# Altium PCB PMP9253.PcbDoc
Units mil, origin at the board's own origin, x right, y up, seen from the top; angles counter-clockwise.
Board outline 3700 x 3100 mil, 4 copper layers (Top Layer, MidLayer1, MidLayer2, Bottom Layer), stack 90 mil thick; 71 components, 28 nets, 219 pads, 12 vias.
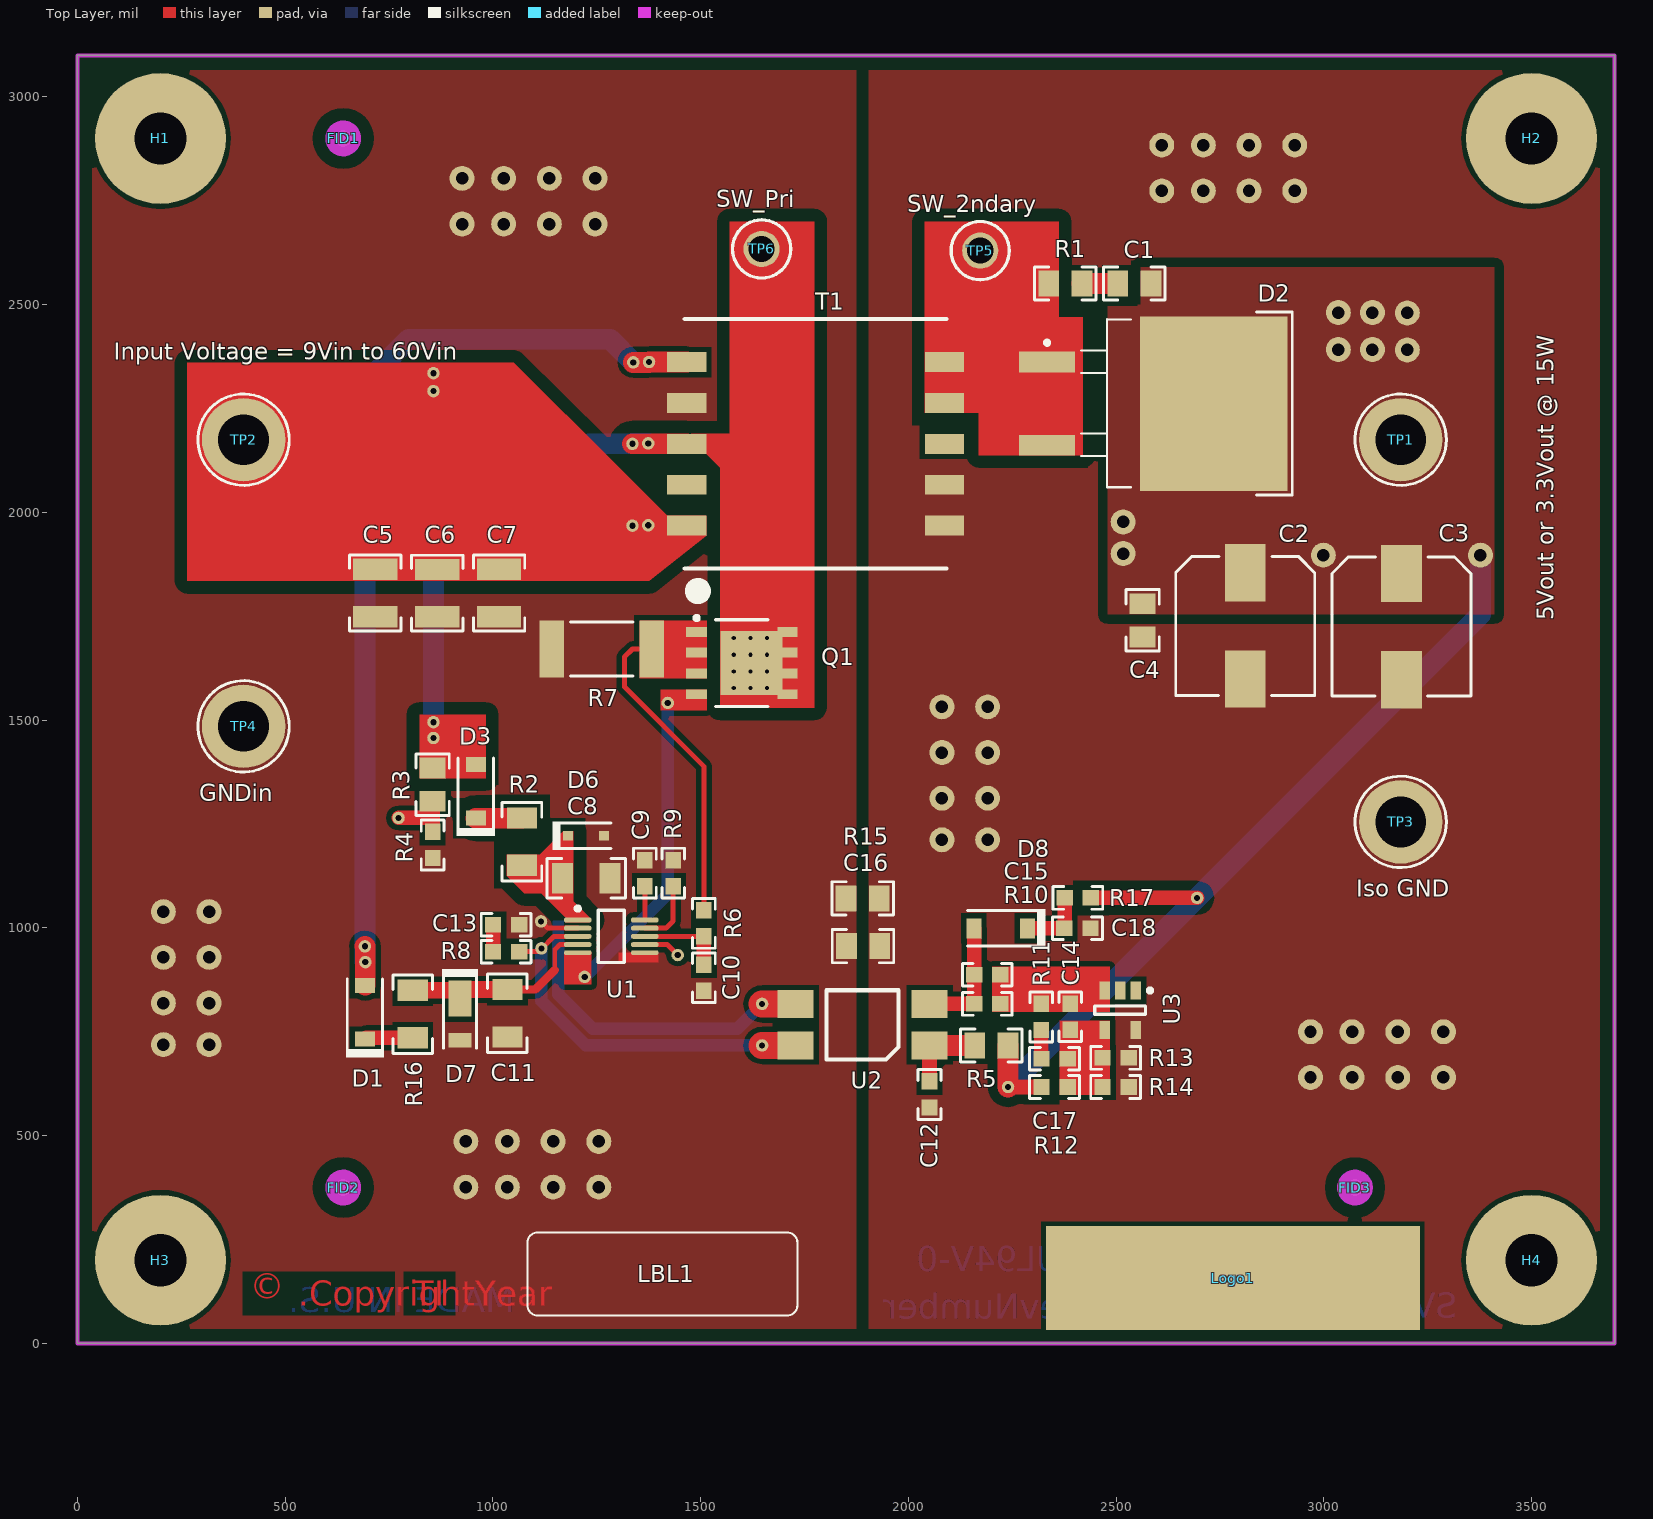
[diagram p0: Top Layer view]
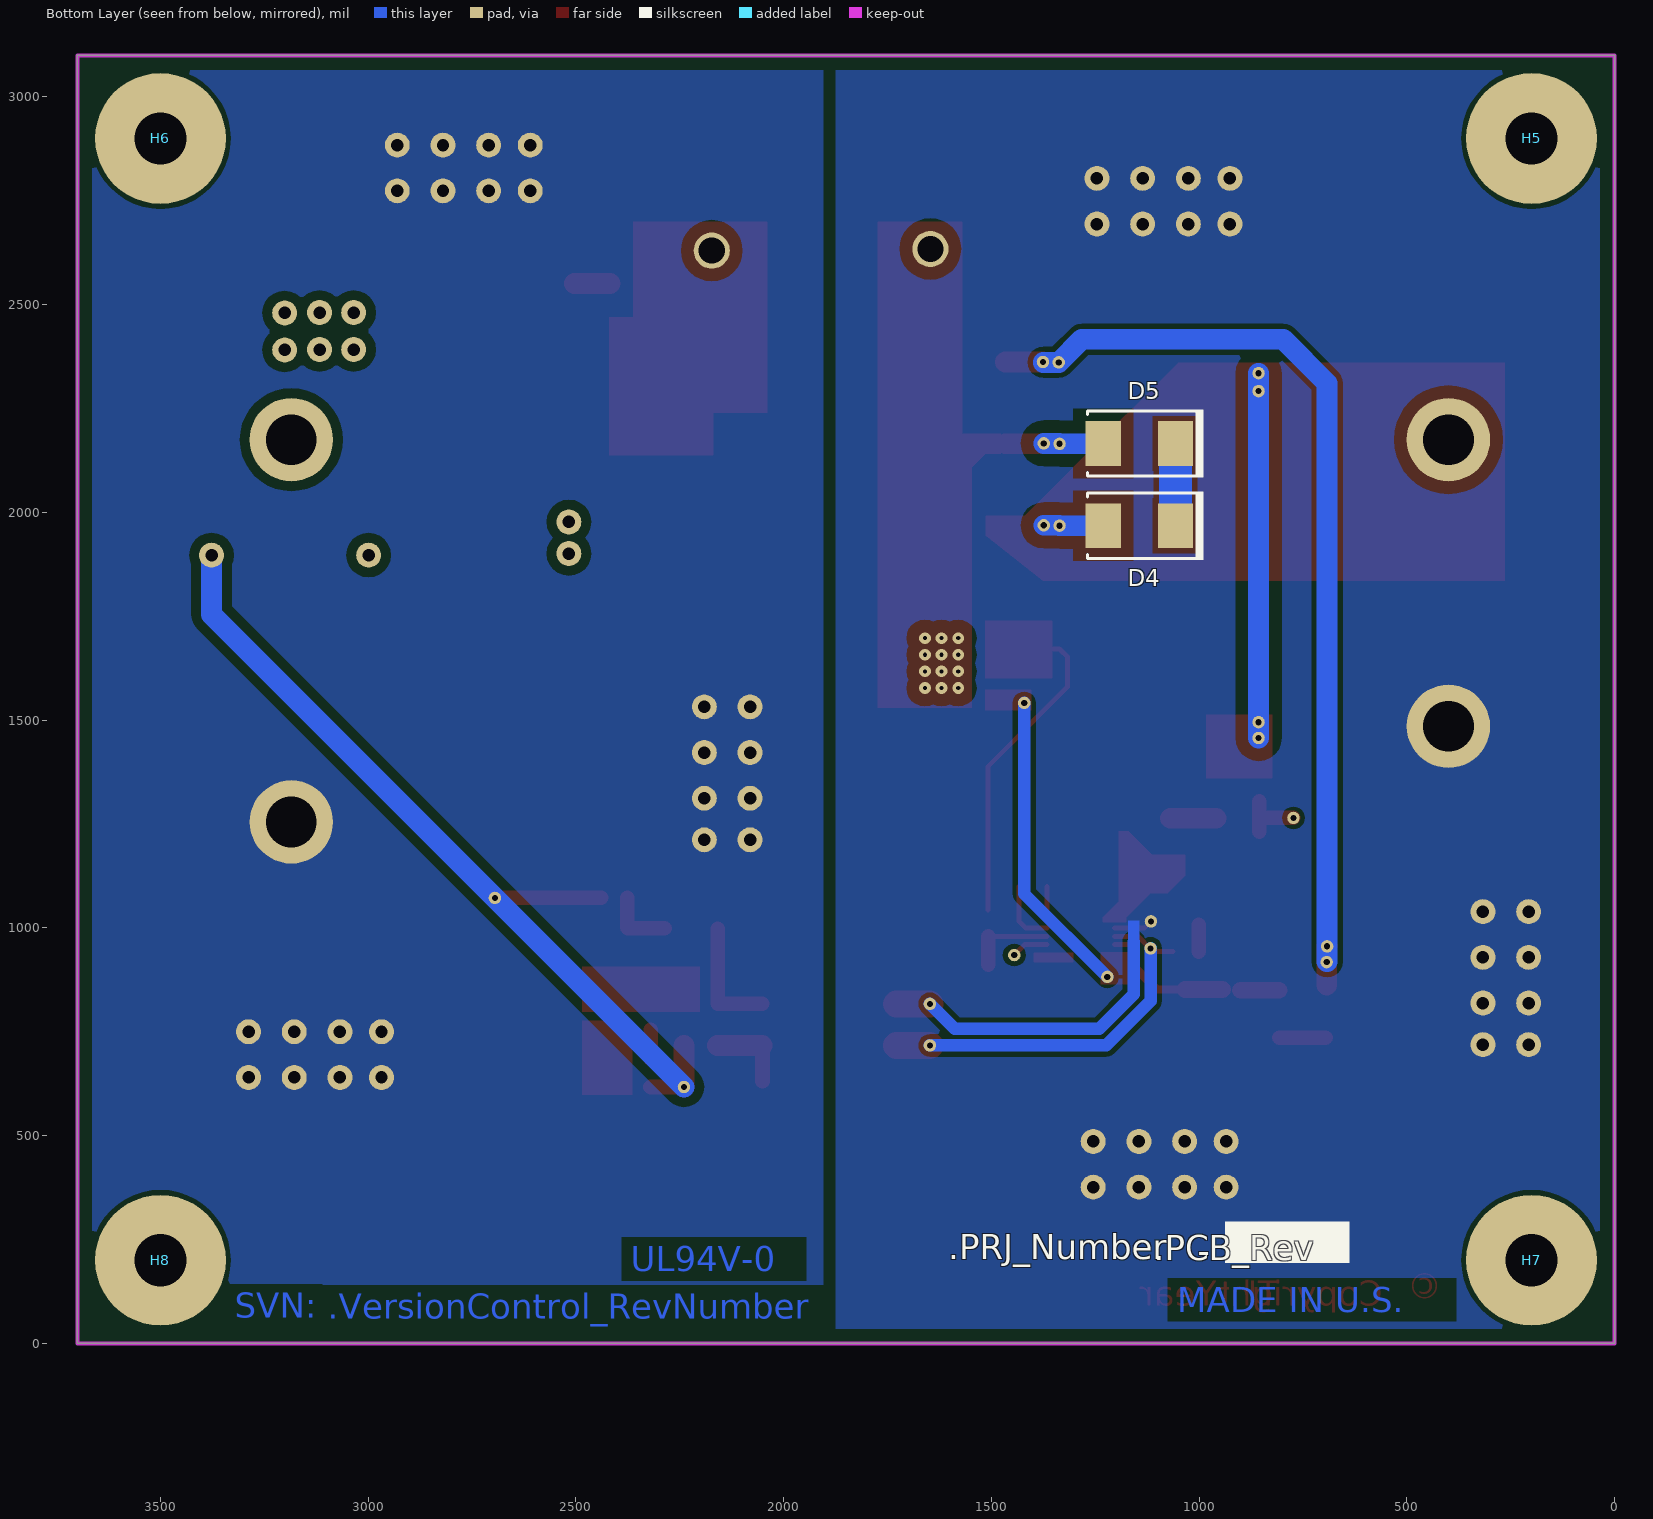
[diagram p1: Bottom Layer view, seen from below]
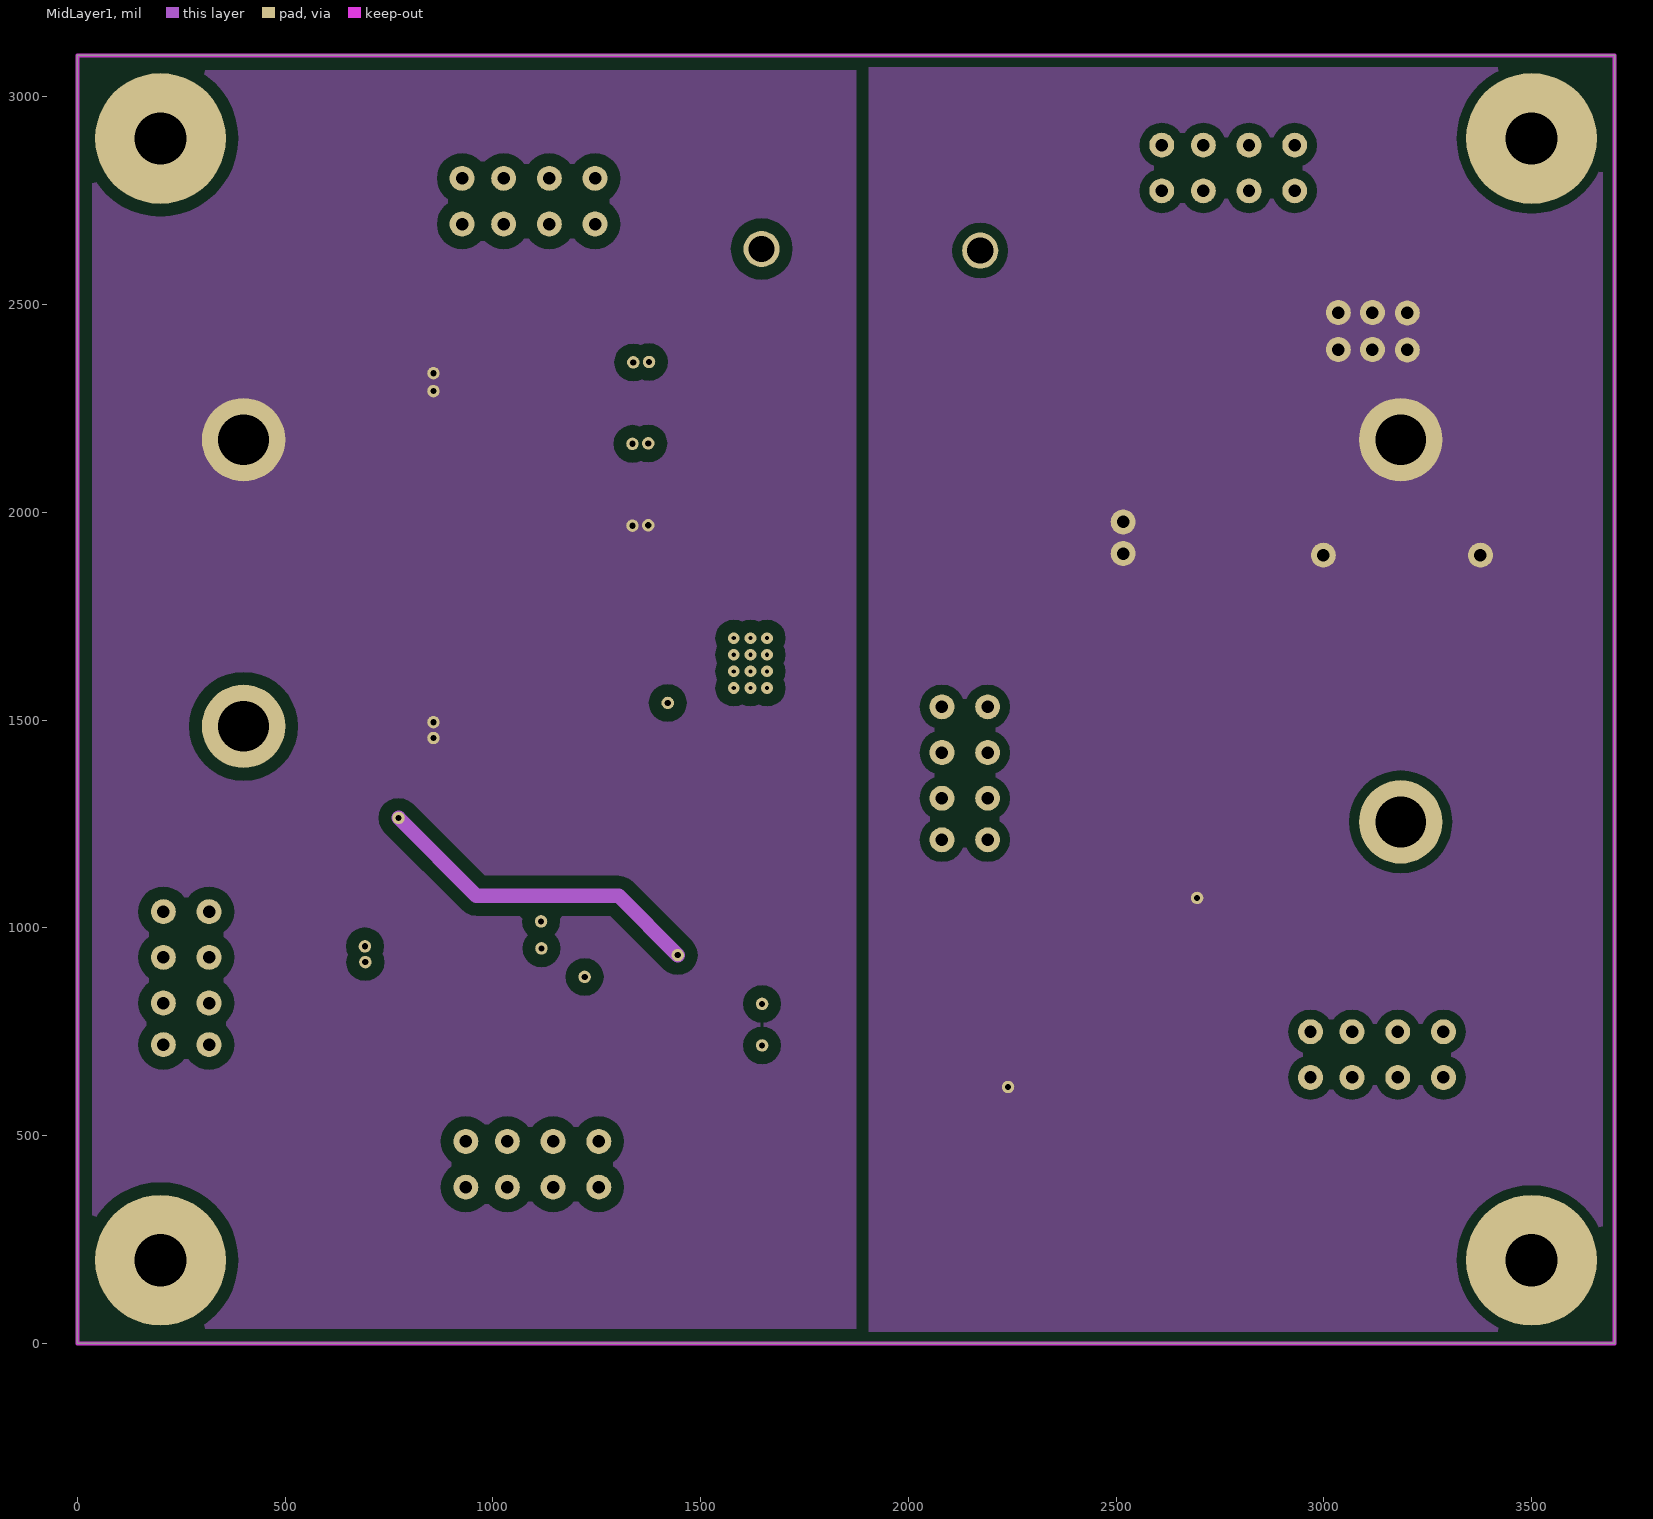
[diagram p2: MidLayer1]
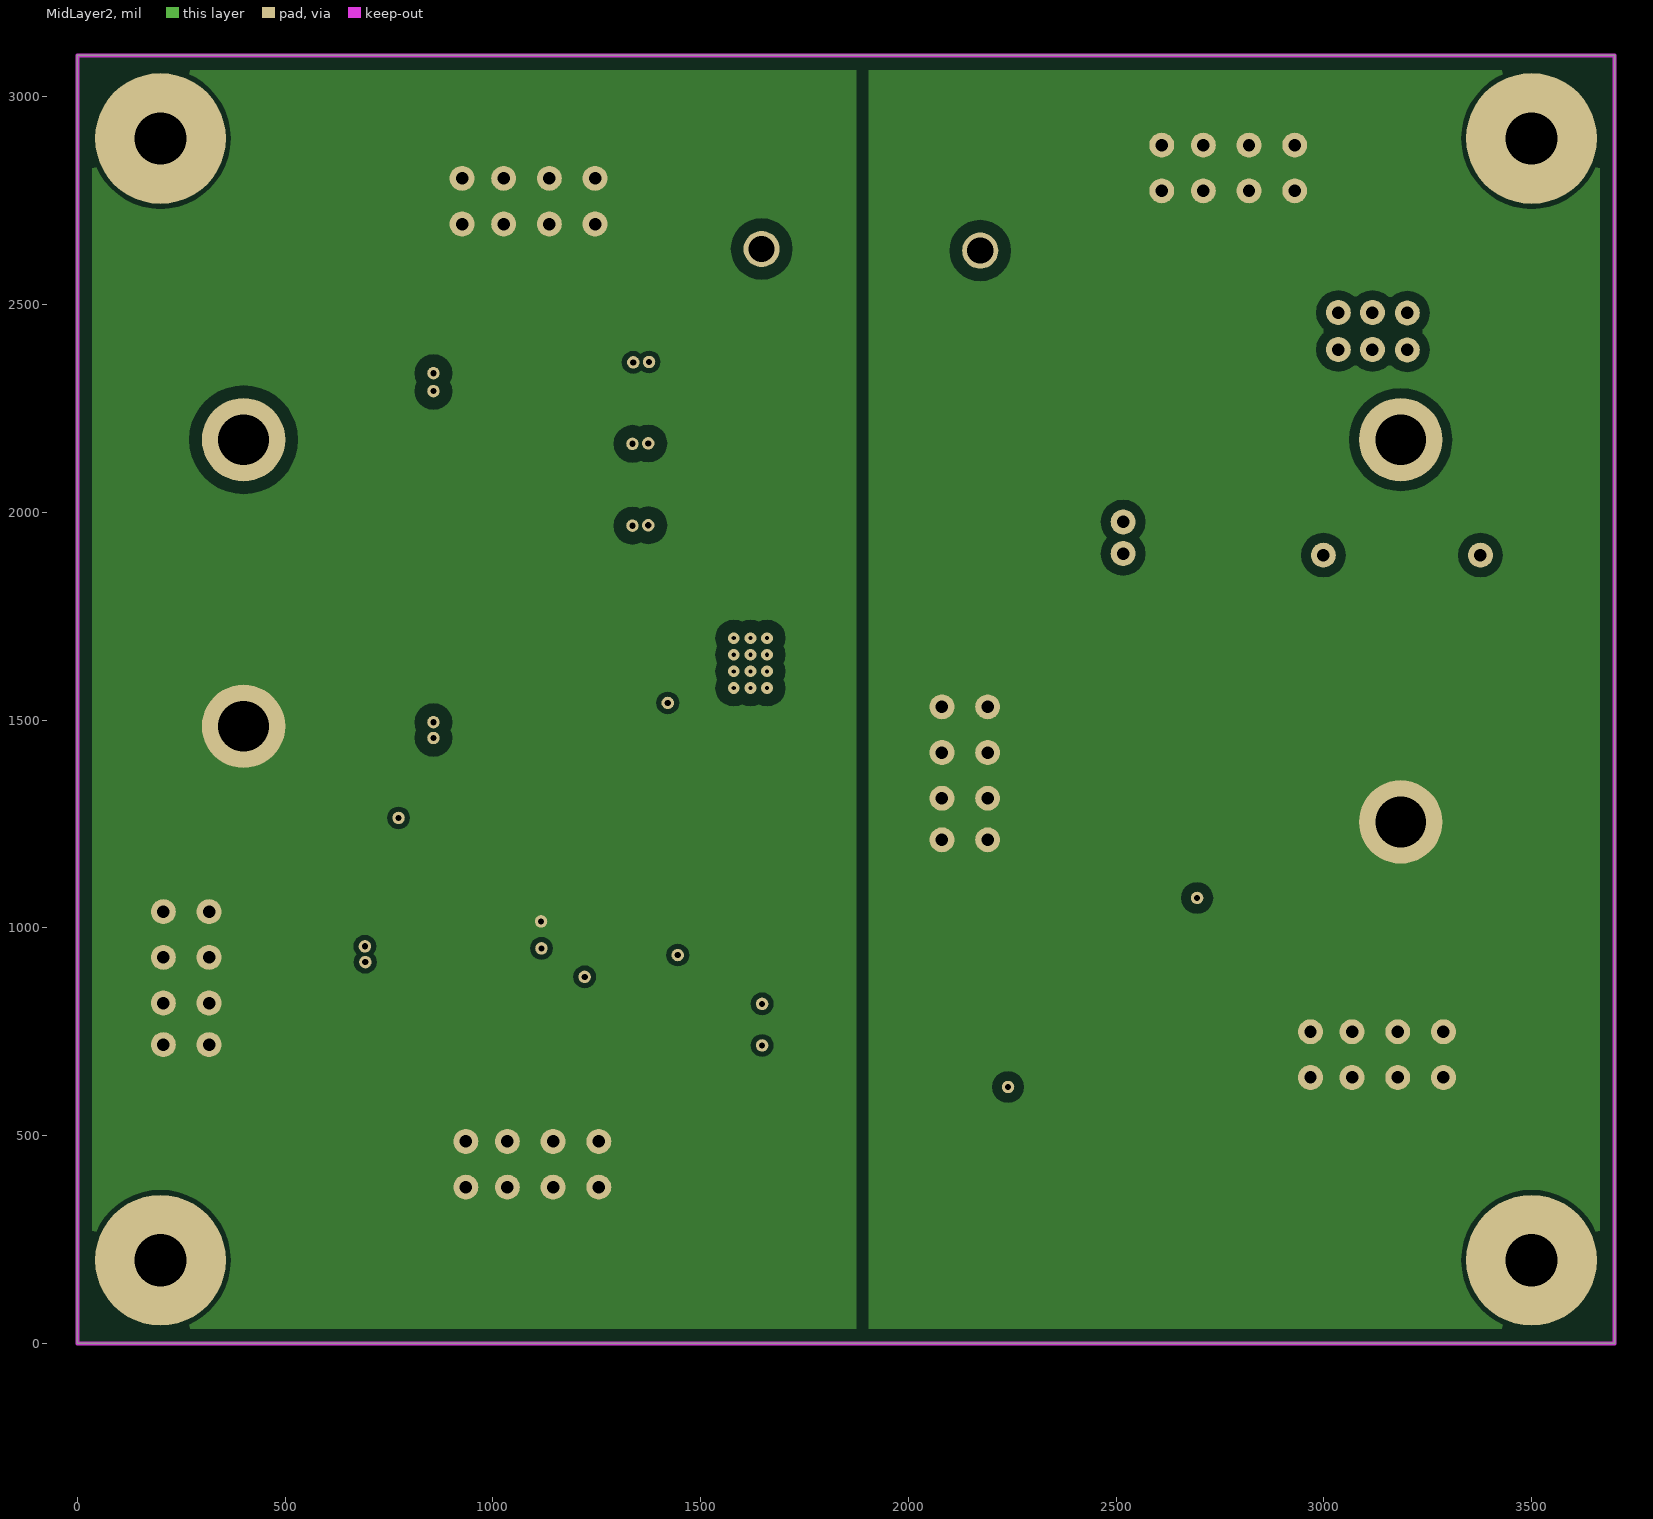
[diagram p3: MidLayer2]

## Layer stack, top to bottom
Top Solder: solder mask 0.4, Solder Resist, Dk 3.5
Top Layer: signal copper 1.4
Dielectric1: core 59.2, FR-4, Dk 4.8
MidLayer1: signal copper 1.4
Dielectric2: prepreg 12.6, FR-4, Dk 4.8
MidLayer2: signal copper 1.4
Dielectric3: core 12.6, FR-4, Dk 4.8
Bottom Layer: signal copper 1.4
Bottom Solder: solder mask 0.4, Solder Resist, Dk 3.5

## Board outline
0,0 3700,0 3700,3100 0,3100

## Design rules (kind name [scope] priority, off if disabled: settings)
AcuteAngle [All] p1: minimum=4.50000000000000E+0001 checktracksonly=FALSE
AssemblyTestPointUsage [All] p1: valid=2
Clearance Clearance_HV_Vout [InNet('VOUT')] p1: gap=23 ignorepadtopadclearanceinfootprint=FALSE except(0: Arc-Hole Track-Hole SMDPad-Hole THPad-Hole Via-Hole Fill-Hole Poly-Hole Region-Hole Text-Hole)
Clearance Clearance_HV_Vout_PreRect [InNet('VOUT_PRERECT')] p2: gap=30 ignorepadtopadclearanceinfootprint=FALSE except(0: Arc-Hole Track-Hole SMDPad-Hole THPad-Hole Via-Hole Fill-Hole Poly-Hole Region-Hole Text-Hole)
Clearance Clearance_HV_SW [InNet('SW')] p3: gap=30 ignorepadtopadclearanceinfootprint=FALSE except(0: Arc-Hole Track-Hole SMDPad-Hole THPad-Hole Via-Hole Fill-Hole Poly-Hole Region-Hole Text-Hole)
Clearance Clearance_HV_VinMain [InNet('VIN_MAIN')] p4: gap=30 ignorepadtopadclearanceinfootprint=FALSE except(0: Arc-Hole Track-Hole SMDPad-Hole THPad-Hole Via-Hole Fill-Hole Poly-Hole Region-Hole Text-Hole)
Clearance Clearance_HV_VinRectified [InNet('VIN_RECTIFIED')] p5: gap=30 ignorepadtopadclearanceinfootprint=FALSE except(0: Arc-Hole Track-Hole SMDPad-Hole THPad-Hole Via-Hole Fill-Hole Poly-Hole Region-Hole Text-Hole)
Clearance Clearance_HV_Vin [InNet('VIN')] p6: gap=30 ignorepadtopadclearanceinfootprint=FALSE except(0: Arc-Hole Track-Hole SMDPad-Hole THPad-Hole Via-Hole Fill-Hole Poly-Hole Region-Hole Text-Hole)
Clearance Clearance_BoardEdge_MountingHoles [OnCopper and InComponentClass('Mounting Holes') vs IsKeepOut] p7: gap=35 ignorepadtopadclearanceinfootprint=FALSE except(0: Arc-Hole Track-Hole SMDPad-Hole THPad-Hole Via-Hole Fill-Hole Poly-Hole Region-Hole Text-Hole)
Clearance Clearance_BoardEdge_Poly [OnCopper and InPoly vs IsKeepOut] p8: gap=30 ignorepadtopadclearanceinfootprint=FALSE except(0: Arc-Hole Track-Hole SMDPad-Hole THPad-Hole Via-Hole Fill-Hole Poly-Hole Region-Hole Text-Hole)
Clearance Clearance_BoardEdge [OnCopper and Not InComponentClass('Logo') and not InComponentClass('FiducialMark') and not InRegion(1000,500,4000,800) and Not IsKeepout vs IsKeepOut] p9: gap=30 ignorepadtopadclearanceinfootprint=FALSE except(0: Arc-Hole Track-Hole SMDPad-Hole THPad-Hole Via-Hole Fill-Hole Poly-Hole Region-Hole Text-Hole)
Clearance Clearance_Poly [InPolygon] p10: gap=12 ignorepadtopadclearanceinfootprint=FALSE except(0: Arc-Hole Track-Hole SMDPad-Hole THPad-Hole Via-Hole Fill-Hole Poly-Hole Region-Hole Text-Hole)
Clearance [All] p11: gap=10 ignorepadtopadclearanceinfootprint=FALSE except(0: Arc-Hole Track-Hole SMDPad-Hole THPad-Hole Via-Hole Fill-Hole Poly-Hole Region-Hole Text-Hole)
ComponentClearance ComponentClearance_Logo [InComponentClass(Logo)] p1: gap=50 collisioncheckmode=3 verticalgap=10 showdistances=FALSE
ComponentClearance ComponentClearance_ScrewToNut [(HasFootprint('NY PMS 440 0025 PH')) vs (HasFootprint('Keystone_1902C'))] p2: gap=5 collisioncheckmode=3 verticalgap=10 showdistances=FALSE
ComponentClearance ComponentClearance_MountingHoles [InComponentClass('Mounting Holes')] p3: gap=250 collisioncheckmode=3 verticalgap=100000 showdistances=FALSE
ComponentClearance ComponentClearance_SmallPassives [HasFootprint('0201*') or HasFootprint('0402*') or HasFootprint('0508') or HasFootprint('0603*') or HasFootprint('0612') or HasFootprint('0805*') or HasFootprint('0815*') or HasFootprint('0830*') or HasFootprint('1206*') or HasFootprint('1210*') or HasFootprint('1808*') or HasFootprint('1812*') or HasFootprint('1825*') or HasFootprint('2010*') or HasFootprint('2220*') or HasFootprint('2225*') or HasFootprint('2512*') or HasFootprint('2728*') or HasFootprint('3518*') vs HasFootprint('0201*') or HasFootprint('0402*') or HasFootprint('0508') or HasFootprint('0603*') or HasFootprint('0612') or HasFootprint('0805*') or HasFootprint('0815*') or HasFootprint('0830*') or HasFootprint('1206*') or HasFootprint('1210*') or HasFootprint('1808*') or HasFootprint('1812*') or HasFootprint('1825*') or HasFootprint('2010*') or HasFootprint('2220*') or HasFootprint('2225*') or HasFootprint('2512*') or HasFootprint('2728*') or HasFootprint('3518*')] p4: gap=20 collisioncheckmode=3 verticalgap=10 showdistances=FALSE
ComponentClearance ComponentClearance_THtoSMT [IsThruComponent vs IsSMTComponent] p5: gap=100 collisioncheckmode=3 verticalgap=100000 showdistances=FALSE
ComponentClearance ComponentClearance_THtoTH [IsThruComponent vs IsThruComponent] p6: gap=118.11 collisioncheckmode=3 verticalgap=100000 showdistances=FALSE
ComponentClearance [All] p7: gap=40 collisioncheckmode=3 verticalgap=10 showdistances=FALSE
DiffPairsRouting [All] p1: maxlimit=100 minlimit=10 mostfreqgap=10 toplayer_minwidth=15 toplayer_maxwidth=15 toplayer_prefwidth=15 midlayer1_minwidth=15 midlayer1_maxwidth=15 midlayer1_prefwidth=15 midlayer2_minwidth=15 midlayer2_maxwidth=15 midlayer2_prefwidth=15 bottomlayer_minwidth=15 bottomlayer_maxwidth=15 bottomlayer_prefwidth=15 maxuncoupledlength=1000
FabricationTestPointUsage TestPointUsage [All] p1: valid=2 allowmultiple=FALSE
FabricationTestpoint Testpoint [All] p1: side=3 testpointundercomponent=TRUE minsize=40 maxsize=100 preferedsize=60 minholesize=0 maxholesize=40 preferedholesize=32 testpointgrid=1 allowsidetop=TRUE allowsidebottom=TRUE usegrid=TRUE gridtolerance=0.01
FanoutControl Fanout_LCC [IsLCC] p1: bgadir=Out bgaviamode=Centered fanoutstyle=Auto fanoutdirection=Alternating viagrid=1 // Fanout_LCC (Default Rule)
FanoutControl Fanout_BGA [IsBGA] p2: bgadir=Out bgaviamode=Centered fanoutstyle=Auto fanoutdirection=Alternating viagrid=1 // Fanout_BGA (Default Rule)
FanoutControl Fanout_Default [All] p4: bgadir=Out bgaviamode=Centered fanoutstyle=Auto fanoutdirection=Alternating viagrid=1 // Fanout_Default (Default Rule)
FanoutControl Fanout_Small [(CompPinCount < 5)] p5: bgadir=Out bgaviamode=Centered fanoutstyle=Auto fanoutdirection=OutThenIn viagrid=1 // Fanout_Small (Default Rule)
HoleSize [All] p1: absolutevalues=TRUE maxlimit=251 minlimit=10 maxpercent=80.000 minpercent=20.000
MinimumAnnularRing [All] p1: minimumring=5
MinimumSolderMaskSliver MinimumSolderMaskSliver_Logo [InComponentClass('Logo') vs InComponentClass('Logo')] p1: minsoldermaskwidth=0.7
MinimumSolderMaskSliver [All] p2: minsoldermaskwidth=4
PlaneClearance [All] p1: clearance=12
PlaneConnect [All] p1: planeconnectstyle=Direct reliefexpansion=10 reliefentries=4 reliefconductorwidth=10 reliefairgap=10
PolygonConnect [All] p1: connectstyle=Direct reliefconductorwidth=10 reliefentries=4 polygonreliefangle="90 Angle" airgapwidth=10
RoutingVias [All] p1: holewidth=16 width=34 viastyle="Through Hole" minholewidth=8 minwidth=26 maxholewidth=40 maxwidth=65
SMDToCorner [All] p1: distance=30000
SilkToSilkClearance [All] p1: silktosilkclearance=5
SilkToSolderMaskClearance SilkscreenOverComponentPads [IsPad] p1: minsilkscreentomaskgap=5 clearancetoexposedcopper=TRUE
SolderMaskExpansion [All] p1: expansion=3
Width [All] p1: maxlimit=100 minlimit=6 preferedwidth=10 checkconnectedcopper=TRUE
15 further rules are at their usual default settings.

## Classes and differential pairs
component class "PMP9253 schematic Rev3": C1 C2 C3 C4 C5 C6 C7 C8 C9 C10 C11 C12 C13 C14 C15 C16 C17 C18 D1 D2 D3 D4 D5 D6 D7 D8 Q1 R1 R2 R3 R4 R5 R6 R7 R8 R9 R10 R11 R12 R13 R14 R15 R16 R17 T1 TP1 TP2 TP3 TP4 TP5 TP6 U1 U2 U3
component class Label: LBL1
component class AssemblyNote: ZZ1 ZZ2 ZZ3 ZZ4
component class FiducialMark: FID1 FID2 FID3
component class PMP9253_Hardware_ANSI-B: FID1 FID2 FID3 H1 H2 H3 H4 H5 H6 H7 H8 LBL1 Logo1 ZZ1 ZZ2 ZZ3 ZZ4
component class Logo: Logo1
component class "Mounting Holes": H1 H2 H3 H4

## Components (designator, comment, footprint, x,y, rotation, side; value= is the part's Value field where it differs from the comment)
C1 "DNP" 0805_HV 2544,2551 r180 top
C2 "Santo, 10SVP330M" SM_RADIAL_8MM 2811,1727 r270 top
C3 "Santo, 10SVP330M" SM_RADIAL_8MM 3187,1725 r270 top
C4 "GRM21BR71A106KE51L" 0805_HV 2564,1740 r270 top
C5 "Yuden, HMK325B7225KN-T" 1210 717,1806 r270 top
C6 "HMK325B7225KN-T" 1210 866,1805.69 r270 top
C7 "HMK325B7225KN-T" 1210 1015,1806 r270 top
C8 "C3216X7R2A105M" 1206 1225,1119.56 r0 top
C9 "C1608C0G1E103J" 0603 1366,1131.56 r90 top
C10 "06035A101JAT2A" 0603 1508,880 r270 top
C11 "GRM31CR71E106KA12L" 1206 1035,794.56 r270 top
C12 "C1608X7R1C105K" 0603 2051,599.01 r90 top
C13 "06033C104JAT2A" 0603 1032,1007.76 r0 top
C14 "06033C101KAT2A" 0603 2390,786.01 r90 top
C15 "DNP" 0603 2190,887.01 r180 top
C16 "C2012C0G2E102J" 0805_HV 1891,956 r180 top
C17 "GRM188R61A474KA61D" 0603 2352,685.01 r180 top
C18 "C1608X7R1C105K" 0603 2407,999 r180 top
D1 "1N4148W-7-F" SOD-123 692,796.56 r90 top
D2 "MBRB1545CT-T" DDPAK 2580,2262 r0 top
D3 "1N4148W-7-F" SOD-123 959,1328.56 r90 top
D4 "DNP" SMB 1144,1968 r0 bottom
D5 "DNP" SMB 1144,2166 r0 bottom
D6 "Diodes Inc, MMSZ5231BS-7-F" sod-323 1224,1221.56 r0 top
D7 "DFLZ12-7" powerDI123 921,779.56 r270 top
D8 "1N4148W-7-F" SOD-123 2222,999 r180 top
FID1 "Fiducial" Fiducial10-20 640,2900 r0 top
FID2 "Fiducial" Fiducial10-20 640,375 r0 top
FID3 "Fiducial" Fiducial10-20 3075,375 r0 top
H1 "NY PMS 440 0025 PH" "NY PMS 440 0025 PH" 200,2900 r0 top locked
H2 "NY PMS 440 0025 PH" "NY PMS 440 0025 PH" 3500,2900 r0 top locked
H3 "NY PMS 440 0025 PH" "NY PMS 440 0025 PH" 200,200 r0 top locked
H4 "NY PMS 440 0025 PH" "NY PMS 440 0025 PH" 3500,200 r0 top locked
H5 "1902C" Keystone_1902C 200,2900 r180 bottom locked
H6 "1902C" Keystone_1902C 3500,2900 r180 bottom locked
H7 "1902C" Keystone_1902C 200,200 r180 bottom locked
H8 "1902C" Keystone_1902C 3500,200 r180 bottom locked
LBL1 "Size: 0.65\" x 0.20 \"" Label_650x200 1408,167 r0 top
Logo1 "Texas Instruments" TI_Stacked_SolderMask_Small 2781,157 r0 top
Q1 "Infineon, BSC190N15NS3" PowerPAK_SO-8 1600,1637.32 r0 top
R1 "DNP" 0805_HV 2378,2551 r0 top
R2 "CRCW12063R32FKEA" 1206 1070,1207.56 r90 top
R3 "CRCW080563K4FKEA" 0805_HV 855,1344.56 r90 top
R4 "CRCW060310K0FKEA" 0603 855,1199.56 r90 top
R5 "10" 0805_HV 2200,717.01 r0 top
R6 "CRCW06031K00FKEA" 0603 1508,1011 r90 top
R7 "RHC2512FTR100" 2512M 1262,1671.32 r0 top
R8 "CRCW06030000Z0EA" 0603 1032,942.56 r0 top
R9 "CRCW060349K9FKEA" 0603 1434,1131.56 r270 top
R10 "CRCW06031K00FKEA" 0603 2190,817.01 r180 top
R11 "CRCW06034K75FKEA" 0603 2320,785.71 r270 top
R12 "CRCW06033K01FKEA" 0603 2352,617.01 r180 top
R13 "CRCW06031K82FKEA" 0603 2499,687.01 r180 top
R14 "CRCW06032K26FKEA" 0603 2499,617.01 r180 top
R15 "CRCW08050000Z0EA" 0805_HV 1890,1071 r0 top
R16 "CRCW120649R9FKEA" 1206 807,792.56 r270 top
R17 "CRCW06033K01FKEA" 0603 2408,1072 r0 top
T1 "PA3856.001NL" PA3856.001NL 1777,2165 r270 top
TP1 "5Vout or 3.3Vout @ 15W" Keystone1503-2 3185,2175 r0 top
TP2 "Input Voltage = 9Vin to 60Vin" Keystone1503-2 400,2175 r0 top
TP3 "Iso GND" Keystone1503-2 3185,1255 r0 top
TP4 "GNDin" Keystone1503-2 400,1485 r0 top
TP5 "SW_2ndary" Keystone5014 2173,2630 r0 top
TP6 "SW_Pri" Keystone5014 1647,2634 r0 top
U1 "LM5022MM" MUB10A_N 1285,979.56 r0 top
U2 "PS2501L-1-A" PS2501L 1890,767.01 r180 top
U3 "TI, LMV431ACM5" MF05A_N 2510,802.01 r270 top
ZZ1 "This Assembly Note is for PCB labels only" AssemblyNoteLabel 185,3938 r0 top
ZZ2 "These assemblies are ESD sensitive, ESD precautions shall be observed." AssemblyNote 185,3829.11 r0 top
ZZ3 "These assemblies must be clean and free from flux and all contaminants. Use of no clean flux is not acceptable." AssemblyNote 185,3740.56 r0 top
ZZ4 "These assemblies must comply with workmanship standards IPC-A-610 Class 2., unless otherwise specified." AssemblyNote 185,3652 r0 top

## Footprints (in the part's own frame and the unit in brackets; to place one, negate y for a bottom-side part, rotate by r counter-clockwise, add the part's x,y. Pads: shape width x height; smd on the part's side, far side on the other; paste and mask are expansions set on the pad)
0603 [mm] "0603 from SM-752 data"
  rect 1x0.95 smd: 1(-0.8,0) 2(0.8,0)
  silkscreen extent -1.52,-0.69 1.52,0.69, body extent -0.87,-0.47 0.87,0.47, height 0.85
0805_HV [mil] "0805 with 30mil clearance between pads"
  rect 50x63 smd: 1(-40,0) 2(40,0)
  silkscreen extent -74,-40 74,40, body extent -43,-29 43,29, height 43
1206 [mm] "1206 from SM-752 data"
  rect 1.3x1.85 smd: 1(-1.45,0) 2(1.45,0)
  silkscreen extent -2.4,-1.21 2.4,1.21, body extent -1.7,-0.9 1.7,0.9, height 1.35
1210 [mm] "1210 from SM-752 data"
  rect 1.3x2.7 smd: 1(-1.45,0) 2(1.45,0)
  silkscreen extent -2.32,-1.57 2.32,1.57, body extent -1.7,-1.35 1.7,1.35, height 1.35
2512M [mm] "Chip Resistor, Body 6.3x3.2mm, IPC Low Density"
  rect 1.5x3.5 smd: 1(-3.05,0) 2(3.05,0)
  silkscreen extent -1.9,-1.65 1.9,1.65, body extent -3.22,-1.67 3.22,1.67, height 0.71
AssemblyNote [mil] "Assembly Note"
AssemblyNoteLabel [mil] "Assembly Note for PCB Labels"
DDPAK [mil] "D2-PAK, 3-Pads, Body 9.7x10.4mm (max), TO-263AB, using Vishay Silionix recommended pad sizes"
  rect 135x49.49 smd: 1(-246.06,100) 3(-246.06,-100)
  rect 355x420 smd paste-181.1: 4(155.51,0)
  silkscreen extent -251,-220 344,220, body extent -295,-202 324,202, height 180
Fiducial10-20 [mm]
  round 1 smd paste-0.5 mask+0.5: 1(0,0)
  Top Layer keep-out circle w1.178: c0,0 r0.5
Keystone1503-2 [mm] "Double Turret"
  round 5.1 hole 3.1: 1(0,0)
  silkscreen extent -2.79,-2.79 2.79,2.79, body extent -2.4,-2.4 2.38,2.4, height 9.22
Keystone5014 [mil] "Keystone Multipurpose loops"
  round 87 hole 63: 1(0,0)
  silkscreen extent -70,-70 70,70, body extent -63,-63 63,62, height 319
Keystone_1902C [mil] "Hex Standoff, 4-40 threaded, nylon"
  body extent -145,-126 146,126, height 501
Label_650x200 [mil] "Thermal Transfer Label"
  silkscreen extent -325,-100 325,100, body extent -325,-100 325,100, height 1
MF05A_N [mm] "SOT23, 5-Leads, Body 2.9x1.6mm, Pitch 0.95mm, Lead Span 2.8mm, IPC Medium Density"
  rect 1.1x0.65 smd: 1(-1.2,0.95) 2(-1.2,0) 3(-1.2,-0.95) 4(1.2,-0.95) 5(1.2,0.95)
  silkscreen extent -1.32,-1.55 0.25,1.95, body extent -0.9,-1.55 0.9,1.55, height 1.19
MUB10A_N [mm] "TSSOP, 10-Leads, Body 3x3mm, Pitch 0.5mm, IPC Medium Density"
  oval 1.7x0.3 smd: 1(-2.05,1) 2(-2.05,0.5) 3(-2.05,0) 4(-2.05,-0.5) 5(-2.05,-1) 6(2.05,-1) 7(2.05,-0.5) 8(2.05,0) 9(2.05,0.5) 10(2.05,1)
  silkscreen extent -2.17,-1.6 0.8,1.82, body extent -1.6,-1.6 1.6,1.6, height 1.09
"NY PMS 440 0025 PH" [mm] "4-40 nylon screw and mounting hole"
  round 8 hole 3.2: 1(0,0)
  body extent -3.3,-3.3 3.3,3.3, height 2.69
PA3856.001NL [mm] "6:3:1:1 Transformer; SMT; 0.1\" Pitch Package"
  rect 1.22x2.4 smd: 1(5,-7.88) 2(2.5,-7.88) 3(0,-7.88) 4(-2.5,-7.88) 5(-5,-7.88) 6(-5,7.88) 7(-2.5,7.88) 8(0,7.88) 9(2.5,7.88) 10(5,7.88)
  silkscreen extent -7.63,-8 9.4,8
powerDI123 [mm] "Diodes Inc recommended land pattern, document number DS30628 Rev. 6-2"
  rect 2.2x1.4 smd: 1(-1.275,0)
  rect 0.9x1.4 smd: 2(1.275,0)
  silkscreen extent -3.1,-1.09 1.76,1.09, body extent -2.38,-0.97 1.52,0.96, height 1
PowerPAK_SO-8 [mil] "Vishay PowerPAK SO-8, Body 5.3x6.0mm (max), Pitch 1.27mm, IPC Medium Density"
  rect 50x24 smd mask+2.99: 1(-109.5,75) 2(-109.5,25) 3(-109.5,-25) 4(-109.5,-75)
  rect 48x24 smd mask+2.99: 5(109.5,-75) 8(109.5,75)
  rect 48x24 smd paste-12 mask+2.99: 6(109.5,-25) 7(109.5,25)
  rect 150x154 smd paste-75 mask+2.99: 9(22.5,0)
  silkscreen extent -114,-104 62,113, body extent -121,-102 121,102, height 43
PS2501L [mm] "NEC optocoupler"
  rect 2.2x1.7 smd: 1(-4.1,1.27) 2(-4.1,-1.27) 3(4.1,-1.27) 4(4.1,1.27)
  silkscreen extent -2.2,-2.1 2.2,2.12, body extent -5,-2.29 5,2.29, height 3.87
SM_RADIAL_8MM [mm] "Nichicon 8x10"
  rect 3.5x2.5 smd: 1(-3.25,0) 2(3.25,0)
  silkscreen extent -4.25,-4.25 4.25,4.25, body extent -4.25,-4.25 4.25,4.25, height 10.5
SMB [mil] "Molded Diode, 2-Leads, Body 5.4x3.6mm, IPC Medium Density, based on OnSemi component dimensions"
  rect 85x107.99 smd: 1(-87.01,0) 2(87.01,0)
  silkscreen extent -155,-82 125,82, body extent -106,-71 106,71, height 91
SOD-123 [mm] "On Semi recommended land pattern"
  rect 0.915x1.22 smd: 1(-1.637,0) 2(1.637,0)
  silkscreen extent -2.74,-1.17 2.03,1.17, body extent -1.93,-0.9 1.93,0.9, height 1.35
sod-323 [mm] "NXP recommended land pattern"
  rect 0.6x0.6 smd paste-0.05: 1(-1.1,0) 2(1.1,0)
  silkscreen extent -2.06,-0.86 1.53,0.86, body extent -1.3,-0.67 1.3,0.68, height 1.1
TI_Stacked_SolderMask_Small [mil]
  rect 900x250 smd paste-125 mask-125: 0(0,0)

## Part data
C1: library part 08055C471KAT2A, "CAP, CERM, 470pF, 50V, +/-10%, X7R, 0805"
C2 C3: library part 10SVP330M, "CAP, OS-CON, 330uF, 10V, +/-20%, 0.017 ohm, 8x10 SMD"
C4: "CAP, CERM, 10uF, 10V, +/-10%, X7R, 0805"
C5: library part HMK325B7225KN-T, "CAP, CERM, 2.2uF, 100V, +/-10%, X7R, 1210"
C6 C7: "CAP, CERM, 2.2uF, 100V, +/-10%, X7R, 1210"
C8: "CAP, CERM, 1uF, 100V, +/-20%, C Series, 1206"
C9: "CAP, CERM, 0.01uF, 25V, +/-5%, C0G/NP0, 0603"
C10: "CAP, CERM, 100pF, 50V, +/-5%, C0G/NP0, 0603"
C11: "CAP, CERM, 10uF, 25V, +/-10%, X7R, 1206"
C12 C18: "CAP, CERM, 1uF, 16V, +/-10%, X7R, 0603"
C13: "CAP, CERM, 0.1uF, 25V, +/-5%, X7R, 0603"
C14: "CAP, CERM, 100pF, 25V, +/-10%, X7R, 0603"
C15: library part C1608X7R1C105K, "CAP, CERM, 1uF, 16V, +/-10%, X7R, 0603"
C16: "CAP, CERM, 1000pF, 250V, +/-5%, C0G/NP0, 0805"
C17: "CAP, CERM, 0.47uF, 10V, +/-10%, X5R, 0603"
D1 D3 D8: "Diode, Ultrafast, 100V, 0.15A, SOD-123"
D2: "Diode, Schottky, 45V, 15A, DDPAK"
D4: library part 1SMB5932BT3G, "Diode, Zener, 20V, 550mW, SMB"
D5: library part MBRS1100T3G, "Diode, Schottky, 100V, 1A, SMB"
D6: library part MMSZ5231BS-7-F, "Diode, Zener, 5.1V, 200mW, SOD-323"
D7: "Diode, Zener, 12V, 1W, PowerDI123"
FID1 FID2 FID3: "Fiducial mark.  There is nothing to buy or mount."
H1 H2 H3 H4: "Machine Screw, Round, #4-40 x 1/4, Nylon, Philips panhead"
H5 H6 H7 H8: "Standoff, Hex, 0.5\"L #4-40 Nylon"
LBL1: library part THT-14-423-10, "Thermal Transfer Printable Labels, 0.650\" W x 0.200\" H - 10,000 per roll"
Logo1: library part TI_Logo, "Texas Instrument Corporate Signature"
Q1: library part SI7178DP, "MOSFET, N-CH, 100V, 60A, PowerPAK SO-8"
R1: library part CRCW0805121RFKEA, "RES, 121 ohm, 1%, 0.125W, 0805"
R2: "RES, 3.32 ohm, 1%, 0.25W, 1206"
R3: "RES, 63.4k ohm, 1%, 0.125W, 0805"
R4: "RES, 10.0k ohm, 1%, 0.1W, 0603"
R5: library part CRCW080510R0JNEA, "RES, 10 ohm, 5%, 0.125W, 0805"
R6 R10: "RES, 1.00k ohm, 1%, 0.1W, 0603"
R7: "RES, 0.1 ohm, 1%, 2W, 2512"
R8: "RES, 0 ohm, 5%, 0.1W, 0603"
R9: "RES, 49.9k ohm, 1%, 0.1W, 0603"
R11: "RES, 4.75k ohm, 1%, 0.1W, 0603"
R12 R17: "RES, 3.01k ohm, 1%, 0.1W, 0603"
R13: "RES, 1.82k ohm, 1%, 0.1W, 0603"
R14: "RES, 2.26k ohm, 1%, 0.1W, 0603"
R15: "RES, 0 ohm, 5%, 0.125W, 0805"
R16: "RES, 49.9 ohm, 1%, 0.25W, 1206"
T1: library part Component_1, "6:3:1:1 Transformer; SMT; 0.1 inch Pitch Footprint"
TP1 TP2 TP3 TP4: library part 1503-2, "Terminal, Turret, TH, Double"
TP5 TP6: library part 5014, "Test Point, Multipurpose, Yellow, TH"
U1: "60V Low Side Controller for Boost and SEPIC, 10-pin MSOP"
U2: "High Isolation Voltage Single Transistor Type OptoCoupler"
U3: library part LMV431ACM5, "Low-Voltage (1.24V) Adjustable Precision Shunt Regulator, 5-pin SOT-23"
ZZ1: library part AssemblyNoteLabel
ZZ2 ZZ3 ZZ4: library part AssemblyNote

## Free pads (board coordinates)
  round 60 hole 30: 0(207,719) 0(926,2804) 0(935,486) 0(2081,1212) 0(2610,2884) 0(2968,750) 0(3035,2392) 0(3035,2481) 1(207,819) 1(1026,2804) 1(1035,486) 1(2081,1312) 1(2710,2884) 1(3068,750) 1(3117,2392) 1(3117,2481) 2(207,929) 2(1136,2804) 2(1145,486) 2(2081,1422) 2(2820,2884) 2(3178,750) 2(3201,2391) 2(3201,2480) 3(207,1039) 3(1246,2804) 3(1255,486) 3(2081,1532) 3(2930,2884) 3(3288,750) 4(317,1039) 4(1246,2694) 4(1255,376) 4(2191,1532) 4(2517,1901) 4(2930,2774) 4(3288,640) 5(317,929) 5(1136,2694) 5(1145,376) 5(2191,1422) 5(2517,1977) 5(2820,2774) 5(2999,1897) 5(3178,640) 5(3377,1897) 6(317,819) 6(1026,2694) 6(1035,376) 6(2191,1312) 6(2710,2774) 6(3068,640) 7(317,719) 7(926,2694) 7(935,376) 7(2191,1212) 7(2610,2774) 7(2968,640)
  round 30 hole 15: 0(692,955.56) 0(693,917.56) 0(773,1264.56) 0(857,1457) 0(857,1495) 0(857,2292) 0(857,2335) 0(1116,1015.56) 0(1117,950.56) 0(1221,882) 0(1336,1968) 0(1336,2165) 0(1338,2361) 0(1374,1969) 0(1374,2166) 0(1376,2362) 0(1421,1541.32) 0(1445,934.56) 0(1648,717) 0(1648,817) 0(2240,617.01) 0(2695,1072)

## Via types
v1: diameter 28, hole 10, Top Layer to Bottom Layer, tented top, 12 vias

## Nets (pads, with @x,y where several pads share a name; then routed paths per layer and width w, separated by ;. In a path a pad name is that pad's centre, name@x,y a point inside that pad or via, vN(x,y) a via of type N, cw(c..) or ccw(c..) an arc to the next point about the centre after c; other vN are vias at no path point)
CLAMP: C1.2 R1.2 | length 86
  Top Layer w50: R1.2 C1.2
COMP: pad.0@1117,950.56 pad.0@1648,717 R8.2 U1.3 U2.4 | length 928
  Top Layer w12: R8.2 pad.0@1110,942.56 ; pad.0@1117.5,950.06 1147,979.56 U1.3
  Top Layer w65: pad.0@1648,717 U2.4
  Bottom Layer w30: pad.0@1117,950.56 1117,824 1224,717 pad.0@1648,717
COMP_CAP: C13.1 R8.1 | length 65.2
  Top Layer w35: R8.1 C13.1
COMP_RC: C17.2 R11.2 | length 68.7
  Top Layer w35: C17.2@2320,685.51 R11.2
CS: C10.1 R6.1 U1.8 | length 209.8
  Top Layer w12: U1.8 R6.1@1507.5,979.56
  Top Layer w35: C10.1 R6.1
CS': Q1.1 Q1.2 Q1.3 R6.2 R7.2 | length 761.9
  Top Layer w12: R7.2 1336,1671.32 1317,1652.32 1317,1580 1508,1389 R6.2
FB: C14.1 C17.1 R12.1 R13.2 R14.2 U3.4
GATE_OUT: pad.0@1221,882 pad.0@1421,1541.32 Q1.4 U1.5 | length 742.2
  Bottom Layer w30: pad.0@1221,882 1421,1082 pad.0@1421,1541.32
GND: C5.2 C6.2 C7.2 C8.2 C9.2 C10.2 C11.2 C13.2 C16.2 D6.2 D7.2 pad.0@207,719 pad.0@926,2804 pad.0@935,486 pad.0@1116,1015.56 pad.1@207,819 pad.1@1026,2804 pad.1@1035,486 pad.2@207,929 pad.2@1136,2804 pad.2@1145,486 pad.3@207,1039 pad.3@1246,2804 pad.3@1255,486 pad.4@317,1039 pad.4@1246,2694 pad.4@1255,376 pad.5@317,929 pad.5@1136,2694 pad.5@1145,376 pad.6@317,819 pad.6@1026,2694 pad.6@1035,376 pad.7@317,719 pad.7@926,2694 pad.7@935,376 R4.1 R7.1 R9.1 R15.1 T1.4 TP4.1 U1.2 U1.6 | length 95
  Top Layer w12: pad.0@1116,1015.56 1132.31,999.25 U1.2
"ISO GND": C2.2 C3.2 C4.2 C12.1 C16.1 C18.1 pad.0@2081,1212 pad.0@2610,2884 pad.0@2968,750 pad.1@2081,1312 pad.1@2710,2884 pad.1@3068,750 pad.2@2081,1422 pad.2@2820,2884 pad.2@3178,750 pad.3@2081,1532 pad.3@2930,2884 pad.3@3288,750 pad.4@2191,1532 pad.4@2930,2774 pad.4@3288,640 pad.5@2191,1422 pad.5@2820,2774 pad.5@3178,640 pad.6@2191,1312 pad.6@2710,2774 pad.6@3068,640 pad.7@2191,1212 pad.7@2610,2774 pad.7@2968,640 R13.1 R14.1 R15.2 T1.9 T1.10 TP3.1 U3.5
NetC18_2: C18.2 D8.1 R17.1 | length 161
  Top Layer w35: D8.1 C18.2 ; C18.2@2376.5,1000 R17.1
OPTO+: C12.2 R5.1 U2.1 | length 194.7
  Top Layer w35: C12.2 U2.1@2051,716.59
  Top Layer w50: U2.1 R5.1
OPTO-: C15.2 D8.2 R10.2 U2.2 | length 288.1
  Top Layer w35: U2.2 R10.2 C15.2 D8.2@2158.51,998.02
OPTO_DRIVE: C14.2 C15.1 R10.1 R11.1 U3.3
OPTO_E_GND: pad.0@1648,817 U2.3 | length 757.6
  Top Layer w65: pad.0@1648,817 U2.3
  Bottom Layer w30: 1157,967.13 1157,840.57 1240.57,757 1588,757 pad.0@1648,817
OV_ZENER: D4.1 D5.1 | length 198
  Bottom Layer w80: D4.1 D5.1
RT: R9.2 U1.9 | length 159
  Top Layer w12: U1.9 1416.69,999.25 1434,1016.56 R9.2
SS: C9.1 U1.10 | length 80.8
  Top Layer w12: U1.10 C9.1@1365.71,1099.77
SW: D5.2 pad.0@1336,2165 pad.0@1374,2166 Q1.5 Q1.6 Q1.7 Q1.8 Q1.9 T1.3 TP6.1 | length 271.8
  Top Layer w50: pad.0@1336,2165 T1.3
  Bottom Layer w50: D5.2@1232.01,2165 pad.0@1336,2165 ; pad.0@1337,2166 pad.0@1374,2166
  other v1: 1580,1577.32 1620,1577.32 1660,1577.32 1580,1617.32 1620,1617.32 1660,1617.32 1580,1657.32 1620,1657.32 1660,1657.32 1580,1697.32 1620,1697.32 1660,1697.32
UVLO: pad.0@773,1264.56 pad.0@1445,934.56 R3.1 R4.2 U1.7 | length 1054
  Top Layer w12: U1.7 1419.68,959.88 pad.0@1445,934.56
  Top Layer w35: pad.0@773,1264.56 855,1264.56 ; R4.2 855,1264.56 ; R3.1 855,1264.56
  MidLayer1 w35: pad.0@773,1264.56 960.56,1077 1302.56,1077 pad.0@1445,934.56
VCC: C11.1 D7.1 R16.1 U1.4 | length 429
  Top Layer w12: 1149,898.56 1149,947.56 1161.32,959.88 U1.4
  Top Layer w20: C11.1 1102.09,851.65 1149,898.56
  Top Layer w40: R16.1 D7.1@901.11,849.65 ; D7.1@942.89,851.65 C11.1
VCC': D1.1 R16.2 | length 111.6
  Top Layer w35: D1.1@695.38,735.47 R16.2
VCC_TXFMR: D1.2 pad.0@692,955.56 pad.0@693,917.56 pad.0@1338,2361 pad.0@1376,2362 T1.5 | length 2364.1
  Top Layer w50: pad.0@692,955.56 693,954.56 693,917.56 D1.2@693,862.03 ; pad.0@1338,2361 pad.0@1375,2361 ; pad.0@1376,2362 T1.5@1466.61,2362
  Bottom Layer w50: pad.0@692,918.56 692,955.56 692,2311 798,2417 1282,2417 1338,2361 pad.0@1375,2361
VIN: C8.1 D6.1 R2.1 U1.1
VIN_MAIN: C5.1 C6.1 C7.1 D3.2 D4.2 pad.0@857,1457 pad.0@857,1495 pad.0@857,2292 pad.0@857,2335 pad.0@1336,1968 pad.0@1374,1969 R3.2 T1.1 TP2.1 | length 1018
  Bottom Layer w50: pad.0@857,1457 pad.0@857,1495 ; pad.0@857,1497 857,2292 pad.0@857,2335 ; D4.2 pad.0@1336,1968 ; pad.0@1337,1969 pad.0@1374,1969
VIN_RECTIFIED: D3.1 R2.2 | length 110.4
  Top Layer w50: D3.1 R2.2@1069.44,1264.09
VOUT: C1.1 C2.1 C3.1 C4.1 D2.4 pad.0@2240,617.01 pad.0@2695,1072 pad.0@3035,2392 pad.0@3035,2481 pad.1@3117,2392 pad.1@3117,2481 pad.2@3201,2391 pad.2@3201,2480 pad.4@2517,1901 pad.5@2517,1977 pad.5@2999,1897 pad.5@3377,1897 R5.2 R12.2 R17.2 TP1.1 | length 2187
  Top Layer w35: pad.0@2240,617.01 R12.2 ; R17.2 pad.0@2695,1072
  Top Layer w50: pad.0@2240,617.01 R5.2
  Bottom Layer w50: pad.0@2240,617.01 3377,1754 pad.5@3377,1897
VOUT_PRERECT: D2.1 D2.3 R1.1 T1.6 T1.7 TP5.1
pads on no net: FID1.1 FID2.1 FID3.1 H1.1 H2.1 H3.1 H4.1 Logo1.0 T1.2 T1.8 U3.1 U3.2

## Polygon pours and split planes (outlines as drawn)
VOUT on Top Layer "Top Layer-Vout" (solid, remove dead copper, pour order 25): 2480,1755 2480,1767 2480,1831 2480,2105 2480,2121 2480,2491 2480,2500 2559,2500 2559,2521 2559,2590 2572,2590 2646,2590 3405,2590 3410,2590 3410,2578 3410,1755 2480,1755
GND on Top Layer "Top Layer-GND" (solid, remove dead copper, pour order 27): 0,3100 1875,3100 1875,3094 1875,0 1863,0 0,0 0,9 0,3100
"ISO GND" on Top Layer "Top Layer-ISO_GND" (solid, remove dead copper, pour order 33): 1905,3100 1909,3100 3700,3100 3700,3098 3700,0 3697,0 1905,0 1905,5 1905,3100
GND on MidLayer2 "MidLayer2-GND" (solid, remove dead copper, pour order 29): 0,3100 3,3100 1875,3100 1875,3091 1875,0 1866,0 0,0 0,3100
"ISO GND" on MidLayer2 "MidLayer2-ISO_GND" (solid, remove dead copper, pour order 35): 1905,3100 1908,3100 3700,3100 3700,3089 3700,0 3698,0 1905,0 1905,3 1905,3100
GND on Bottom Layer "Bottom Layer-GND" (solid, remove dead copper, pour order 31): 0,3100 3,3100 1875,3100 1875,3096 1875,0 1863,0 0,0 0,8 0,3100
"ISO GND" on Bottom Layer "Bottom Layer-ISO_GND" (solid, remove dead copper, pour order 37): 1905,3100 1908,3100 3700,3100 3700,0 1905,0 1905,3 1905,3100
VIN_MAIN on MidLayer1 "MidLayer1-Vin_Main" (solid, remove dead copper, pour order 39): 0,3100 1875,3100 1875,0 0,0 0,3100
VOUT on MidLayer1 "MidLayer1-Vout" (solid, remove dead copper, pour order 41): 1905,3100 3700,3100 3700,0 1905,0 1905,3100

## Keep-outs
Keep-Out Layer:
  the board outline again, w10
  text ".Layer_Name" at 577,-858.49 h60

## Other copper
Top Layer:
  rectangle net GATE_OUT: 1171,863.56 1238,941.56
  region net CS': 1353,1740.32 1353,1600.32 1515,1600.32 1515,1740.32
  region net GATE_OUT: 1403,1573.32 1403,1523.32 1516,1523.32 1516,1573.32
  rectangle net FB: 2364,598.3 2486,777.01
  rectangle net OPTO_DRIVE: 2202,798.01 2485,907.01
  rectangle net GND: 1303,916.56 1399,940.56
  rectangle net VIN_MAIN: 823,1360 983,1513
  region net SW: 1477,2189 1570,2189 1570,2700 1774,2700 1774,2270 1773,1967 1773,1530 1547,1530 1547,2108 1514,2141 1477,2141
  region net VIN_MAIN: 265,1835 1377,1835 1514,1944 1514,1992 1420,1992 1301,2111 1050,2360 265,2360
  region net VIN: 1034,1125.56 1076,1083.56 1193,1083.56 1194,1084.56 1194,1232.56 1169,1232.56 1113,1176.56 1034,1176.56
  region net VIN: 1194,1089.56 1194,1063.56 1232,1025.56 1232,1013.56 1175,1013.56 1175,1024.56 1112,1087.56 1112,1089.56
  region net VOUT_PRERECT: 2420,2138 2420,2470 2362,2470 2362,2700 2040,2700 2040,2240 2170,2240 2170,2138
  text ".CopyrightYear" at 532,90 h60
  text "TI" at 808,90 h60
  text "©" at 415,86.48 h105
  text ".Layer_Name" at 577,-858.49 h60
Bottom Layer:
  rectangle net OPTO_E_GND: 1143,954 1171,1018
  text "UL94V-0" at 2367.7,172.99 h60
  text "MADE IN U.S." at 1053,75 h60
  text "SVN:" at 3321,62 h60
  text ".VersionControl_RevNumber" at 3097,59 h60
  text ".Layer_Name" at 577,-858.49 h60

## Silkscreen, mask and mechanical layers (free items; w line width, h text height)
Top Overlay:
  text "This document can handle board shapes up to 7.9in x 10in, although" at 480,7475 h60
  text "our panel vendors top out at 7in x 10in." at 480,7350.94 h60
  text "To re-size the board shape, do the following:" at 535,7226.88 h60
  text "Select lines on M1 Board Outline and delete (easy in single layer mode...shift+s)" at 595,7102.82 h60
  text "Draw a rectangle using lines (example will be for a 4\" x 6\" board" at 595,6978.76 h60
  text "Enter Place Line mode (keyboard pl)" at 805,6854.71 h60
  text "keyboard jo to jump to origin, hit enter" at 805,6730.65 h60
  text "keyboard jl to jump to location, set x to 6000, hit enter twice" at 805,6606.59 h60
  text "keyboard jl to jump to location, set x to 6000 and y to 4000, hit enter twice" at 805,6482.53 h60
  text "keyboard jl to jump to location, set x to 0 and y to 4000, hit enter twice" at 805,6358.47 h60
  text "keyboard jo to jump to origin, hit enter" at 805,6234.41 h60
  text "Hit ESC twice to exit place line mode" at 805,6110.35 h60
  text "Select lines on M1 Board Outline" at 595,5966.3 h60
  text "Menu Design|Board Shape|Define from Selected Objects (keyboard dsd)" at 595,5862.24 h60
  text "To define a Keep-Out that mirrors the board outline:" at 480,5738.18 h60
  text "Menu Design|Board Shape|Create Primitives From Board Shape (keyboard dsp)" at 595,5614.12 h60
  text "Set the Keep-Out Layer as the layer, set width as preferred" at 805,5490.06 h60
  text "Ensure Route Tool Outline is selected, hit enter" at 805,5366 h60
  text "If you re-size the board, don't forget to move the drill table strings on the" at 480,5043 h60
  text "Drill Drawing Layer...they should be just to the right of your board shape" at 673,4937 h60
  text ".Layer_Name" at 577,-858.49 h60
Bottom Overlay:
  rectangle: 638,193 938,293
  text ".PRJ_Number" at 1604,203 h60
  text ".PCB_Rev" at 1109,200 h60
  text "-" at 1003,192.5 h60
  text ".Layer_Name" at 577,-858.49 h60
Top Paste:
  text ".Layer_Name" at 577,-858.49 h60
Bottom Paste:
  text ".Layer_Name" at 577,-858.49 h60
Top Solder:
  text ".Layer_Name" at 577,-858.49 h60
  text ".Layer_Name" at 577,-858.49 h60
Bottom Solder:
  text ".Layer_Name" at 577,-858.49 h60
Drill Guide:
  text ".Layer_Name" at 577,-858.49 h60
M1 Board Outline:
  the board outline again, w10
  text ".Layer_Name" at 577,-858.49 h60
M2 Board Dimensions:
  rectangle: 124.5,-410.5 499.5,-285.5
  rectangle: -0.5,-285.5 124.5,-160.5
  lines w7: -0.5,-285.5 999.5,-285.5 ; 124.5,-410.5 124.5,-160.5 ; 249.5,-410.5 249.5,-160.5 ; 499.5,-410.5 499.5,-160.5 ; 749.5,-410.5 749.5,-160.5 ; -0.5,-410.5 -0.5,-160.5 999.5,-160.5 999.5,-410.5 -0.5,-410.5
  lines w10: -0.5,-475.5 -0.5,-455.5 ; 59.5,-485.5 -0.5,-465.5 ; 59.5,-445.5 -0.5,-465.5 ; 223.58,-465.5 -0.5,-465.5 ; 775.42,-465.5 999.5,-465.5 ; 939.5,-485.5 999.5,-465.5 ; 939.5,-445.5 999.5,-465.5 ; 999.5,-475.5 999.5,-455.5
  text "1000 (mil)" at 233.58,-501.49 h60
  text ".Layer_Name" at 577,-858.49 h60
M3 3D STEP Top:
  text ".Layer_Name" at 577,-858.49 h60
M4 3D STEP Bottom:
  text ".Layer_Name" at 577,-858.49 h60
M5 Assembly Top:
  lines w7: 5139,110.5 6264,110.5 ; 5139,233 6261.5,233 ; 5454,-9.5 5454,353 ; 5839,-9.5 5139,-9.5 ; 5839,353 5139,353 ; 5139,-9.5 5139,353 ; 5139,-9.5 6264,-9.5 6264,353 5139,353
  lines w10: -292,-930.17 6308,-930.17 ; -292,-726.83 6310,-726.83 ; -292,-523.5 -292,-1133.5 3713,-1133.5 6310,-1133.5 6310,-523.5 -291.5,-523.5 -291.5,-1133.5 1284,-1133.5 ; 2173,-1133.5 2173,-523.5 ; 3440,-726.83 3440,-523.5 ; 4280,-726.83 4280,-523.5 ; 4902,-1140 4902,-937.17
  text "TABLE 1" at 5526.5,388 h40
  text "Variant" at 5164,278 h40
  text "Label text" at 5599,278 h40
  text "001" at 5231.5,158 h40
  text "ChangeMe!" at 5509,155.5 h40
  text "002" at 5231.5,33 h40
  text "ChangeMe!" at 5504,30.5 h40
  text "COMPONENTS MARKED 'DNP' SHOULD NOT BE POPULATED." at 1153.5,-318.5 h60
  text "ASSEMBLY VARIANT:" at 1153,-434 h60
  text ".VariantName" at 2189,-434 h60
  text "PCB VIEWED FROM TOP SIDE" at -228.5,-655.67 h60
  text "BOARD #:" at 2248,-655.67 h60
  text ".PRJ_Number" at 2793.5,-655.67 h60
  text "REV:" at 3638,-655.67 h60
  text ".PCB_Rev" at 3929.5,-655.67 h60
  text "SVN REV:" at 4476,-655.67 h60
  text ".VersionControl_RevNumber" at 4982,-655.67 h60
  text "IGNORE ->" at -228.5,-858.49 h60
  text "PLOT NAME =" at -228.5,-1064.34 h60
  text ".plot_File_Name" at 577,-1064.34 h60
  text "GENERATED    :" at 2250,-1064.34 h60
  text ".Print_Date" at 3119.5,-1064.34 h60
  text ".Print_Time" at 3848.5,-1064.34 h60
  text "TEXAS INSTRUMENTS" at 5113,-1064.34 h60
M6 Assembly Bottom:
  lines w10: -292.5,-727.33 6309.5,-727.33 ; -290.5,-930.67 6309.5,-930.67 ; 1115.5,-1140.5 1115.5,-937.67 ; 1737.5,-727.33 1737.5,-524 ; 2577.5,-727.33 2577.5,-524 ; 3844.5,-1134 3844.5,-524 ; 4733.5,-1134 6309,-1134 6309,-524 -292.5,-524 -292.5,-1134 2304.5,-1134 6309.5,-1134 6309.5,-524
  text "COMPONENTS MARKED 'DNP' SHOULD NOT BE POPULATED." at 6102,-318 h60
  text ".VariantName" at 5058,-434 h60
  text "ASSEMBLY VARIANT:" at 6097,-434 h60
  text ".VersionControl_RevNumber" at 1035.5,-656.17 h60
  text "SVN REV:" at 1541.5,-656.17 h60
  text ".PCB_Rev" at 2088,-656.17 h60
  text "REV:" at 2379.5,-656.17 h60
  text ".PRJ_Number" at 3224,-656.17 h60
  text "BOARD #:" at 3769.5,-656.17 h60
  text "PCB VIEWED FROM BOTTOM SIDE" at 6246,-656.17 h60
  text "IGNORE ->" at 2547.85,-858.49 h60
  text "TEXAS INSTRUMENTS" at 904.5,-1064.84 h60
  text ".Print_Time" at 2169,-1064.84 h60
  text ".Print_Date" at 2898,-1064.84 h60
  text "GENERATED    :" at 3767.5,-1064.84 h60
  text ".plot_File_Name" at 5440.5,-1064.84 h60
  text "PLOT NAME =" at 6246,-1064.84 h60
M9 Title Sheet:
  drawing of 57 lines, arcs and shapes, not listed
  text "1" at 739.84,8036.5 h70
  text "2" at 3235.5,8036.5 h70
  text "3" at 5724.84,8036.5 h70
  text "4" at 8231.51,8036.5 h70
  text "5" at 10730.5,8036.5 h70
  text "6" at 13235.5,8036.5 h70
  text "A" at -416.5,6893.5 h70
  text "A" at 14383.5,6893.5 h70
  text "B" at -416.5,4513.5 h70
  text "B" at 14383.5,4513.5 h70
  text "C" at -416.5,2138.5 h70
  text "C" at 14383.5,2138.5 h70
  text "PROJECT TITLE:" at 11343.5,277.5 h45
  text ".PRJ_Title" at 11393.5,144.17 h70
  text "DESIGNED FOR:" at 11343.5,-23.5 h45
  text ".PRJ_Customer" at 11393.5,-163.5 h70
  text "D" at -416.5,-231.5 h70
  text "D" at 14383.5,-231.5 h70
  text "FILE NAME:" at 11343.5,-323.5 h45
  text ".PCB_File_Name_No_Path" at 11393.5,-443.5 h70
  text "Texas Instruments (TI) and/or its licensors do not warrant the accuracy or completeness of this specification" at 6374,-605.34 h45
  text "ENGINEER:" at 11343.5,-613.5 h45
  text "LAYOUT BY:" at 12848.5,-613.5 h45
  text "or any information contained therein. TI and/or its licensors do not warrant that this design will meet" at 6329.01,-718 h45
  text ".PRJ_Engineer" at 11393.5,-768.49 h70
  text ".PCB_Layout" at 12899,-768.49 h70
  text "the specifications, will be suitable for your application or fit for any particular purpose, or will operate in" at 6329.01,-830.67 h45
  text ".Layer_Name" at 577,-858.49 h60
  text "ALTIUM DESIGNER VERSION:" at 12848.5,-923.5 h45
  text "an implementation. TI and/or its licensors do not warrant that the design is production worthy. You should" at 6329.01,-943.33 h45
  text "completely validate and test your design implementation to confirm the system functionality for your application." at 6374,-1056 h45
  text ".print_Scale" at 11393.5,-1056.83 h70
  text ".Application_BuildNumber" at 12899,-1056.83 h70
  text "1" at 739.84,-1263.5 h70
  text "2" at 3235.5,-1263.5 h70
  text "3" at 5724.84,-1263.5 h70
  text "4" at 8231.51,-1263.5 h70
  text "5" at 10730.5,-1263.5 h70
  text "6" at 13235.5,-1263.5 h70
M10 Fab Notes:
  drawing of 212 lines, arcs and shapes, not listed
  text "DESIGN INFORMATION" at 12381.02,6810 h60
  text "(REFER ALSO ARRAY/PANEL PROFILING INFORMATION)" at 12019.46,6648.29 h60
  text "BOARD SIZE" at 11333.46,6644 h60
  text "3700MIL" at 11795.78,6516.18 h60
  text "X" at 12301.46,6516.18 h60
  text "3100MIL" at 12532.78,6516.18 h60
  text "Number of Layers :" at 11736.46,6319 h60
  text "4" at 12831.27,6309 h60
  text "MIN. TRACK WIDTH:" at 11736.46,6180 h60
  text "12" at 12832.7,6180 h60
  text "MIL" at 12987.46,6180 h60
  text "MIN. CLEARANCE:" at 11736.46,6048 h60
  text "12" at 12832.7,6048 h60
  text "MIL" at 12987.46,6048 h60
  text "MIN. VIA PAD SIZE:" at 11736.46,5916 h60
  text "15" at 12802.71,5916 h60
  text "MIL" at 12987.46,5916 h60
  text "0.05mm (2MIL)" at 12431.46,5774.29 h60
  text "MINIMUM ANNULAR RING" at 11407.23,5770 h60
  text "EXTERNAL" at 13139.46,5770 h60
  text "PER" at 11607.23,5652 h60
  text "IPC-D-275 CLASS 2 LEVEL C" at 11827.23,5652 h60
  text "MIL, HOLES" at 13315.46,5539.71 h60
  text "+/-" at 12923,5539 h60
  text "+/-" at 13777,5539 h60
  text "REGISTRATION TOLERANCES:" at 11407.23,5534 h60
  text "METAL" at 12607,5534 h60
  text "5" at 13183.2,5534 h60
  text "3" at 14016.2,5534 h60
  text "MIL" at 14132.46,5534 h60
  text "MATERIAL:" at 11332.46,5324.54 h60
  text "FR-4 High Tg" at 12318.9,5184.21 h60
  text "FR-408" at 11753.46,5175.64 h60
  text "X" at 12165.46,5175.64 h60
  text "OTHER" at 13241.46,5175.64 h60
  text "62 MIL (1.6mm) +/-10%" at 12073.56,5012.92 h60
  text "THICKNESS:" at 11407.23,5008.64 h60
  text "X" at 11945.4,5008.64 h60
  text "OTHER" at 13358.46,5008.64 h60
  text "TOLERANCE:" at 11407.23,4850.64 h60
  text "X" at 12246.53,4850.64 h60
  text "ANSI IPC-6012 TYPE 3 CLASS 2" at 12433.48,4850.64 h60
  text "OTHER +/-" at 12433.46,4694.64 h60
  text "BOW & TWIST:" at 11407.23,4537.64 h60
  text "X" at 12246.53,4537.64 h60
  text "ANSI IPC-6012 TYPE 3 CLASS 2" at 12433.48,4537.64 h60
  text "OTHER +/-" at 12433.46,4379.13 h60
  text "COPPER THICKNESS (FINISHED):" at 11332.46,4243.64 h60
  text "1.4MIL (1oz)" at 12212.46,4090.92 h60
  text "2MIL (1.4oz)" at 12979.46,4090.92 h60
  text "2.8MIL (2oz)" at 13706.46,4090.92 h60
  text "OUTER:" at 11689.46,4086.64 h60
  text "X" at 12084,4086 h60
  text "1.4MIL (1oz)" at 12212.46,3933.92 h60
  text "2.8MIL (2oz)" at 12979.46,3933.92 h60
  text "N/A" at 13706,3934.29 h60
  text "INNER SIGNAL:" at 11400.38,3929.64 h60
  text "X" at 12085.42,3929.64 h60
  text "DRILLING:" at 11332.46,3790.64 h60
  text "REFERENCE:" at 11407.23,3673.64 h60
  text "X" at 12055.46,3673.64 h60
  text "AS SHOWN" at 12242.46,3673.64 h60
  text "X" at 12956.46,3673.64 h60
  text "NC_DRILL FILES" at 13093.46,3673.64 h60
  text "PTH MIN COPPER THICKNESS:" at 11407.23,3515.64 h60
  text "X" at 12757.46,3515.64 h60
  text "1MIL" at 12894.46,3515.64 h60
  text "OTHER" at 13391.46,3515.64 h60
  text "BOARD FINISH:" at 11332.46,3356.64 h60
  text "SILKSCREEN:" at 11487.68,3238.64 h60
  text "X" at 12436.46,3238.64 h60
  text "TOP" at 12562.46,3238.64 h60
  text "X" at 12946.46,3238.64 h60
  text "BOTTOM" at 13073.46,3238.64 h60
  text "SILKSCREEN COLOR:" at 11487.68,3071.64 h60
  text "X" at 12435.42,3071.64 h60
  text "WHITE" at 12562.46,3071.64 h60
  text "OTHER" at 13073.46,3071.64 h60
  text "SOLDER RESIST COLOR:" at 11487.68,2901.64 h60
  text "X" at 12055.42,2742.44 h60
  text "GREEN" at 12182.46,2742.44 h60
  text "BLUE" at 12773.46,2742.44 h60
  text "OTHER" at 13311.46,2742.44 h60
  text "IMMERSION GOLD (ENIG)" at 12393.46,2553.92 h60
  text "ENEPIG" at 13731,2550.64 h60
  text "SURFACE FINISH:" at 11332.46,2549.64 h60
  text "X" at 12206.51,2549.64 h60
  text "IMM. TIN/SILVER OR EQUIV" at 11662,2392.64 h60
  text "OTHER" at 13093.46,2392.64 h60
  text "ARRAY/PANEL:" at 11332.46,2213.64 h60
  text "CUT AND TRIM PER MECH LAYER 1" at 12393.46,2209.35 h60
  text "N.C. ROUTE" at 12393.46,2057.64 h60
  text "X" at 13072.46,2057.64 h60
  text "V. SCORE" at 13259.46,2057.64 h60
  text "CERTIFICATION:" at 11332.46,1920.64 h60
  text "MATERIALS AND WORKMANSHIP FOR ALL PCBS" at 12057.46,1920.64 h60
  text "TO MEET OR EXCEED THE REQUIREMENTS OF:" at 12057.46,1822.64 h60
  text "X" at 11683.96,1686.13 h60
  text "ANSI IPC-A-600F CLASS ->" at 11822.96,1686.13 h60
  text "X" at 13462.02,1686.13 h60
  text "2" at 13580.96,1686.14 h60
  text "1" at 13265.96,1684.64 h60
  text "3" at 13934.96,1684.64 h60
  text "X" at 11686.02,1526.64 h60
  text "UL 94V-0" at 11822.96,1526.64 h60
  text "X" at 12498.02,1526.64 h60
  text "RoHS" at 12634.96,1526.64 h60
  text "OTHER" at 13279.36,1526.64 h60
  text "PER ORDER" at 13676.42,1526.64 h60
  text "ADDITIONAL REQUIREMENTS:" at 11332.46,1385.64 h60
  text "MICROSECTION:" at 11407.23,1270.64 h60
  text "YES" at 12312.96,1270.64 h60
  text "REQUIRED" at 13174.46,1114.49 h60
  text "BARE BOARD ELEC. TEST:" at 11407.23,1111.64 h60
  text "NONE" at 12712.96,1111.64 h60
  text "X" at 13047.46,1111.64 h60
  text "PER ORDER" at 13766.46,1111.64 h60
  text "MANUFACTURER'S UL:" at 11407.23,954.64 h60
  text "RAIL" at 12572.96,950.35 h60
  text "METAL" at 13064.77,950.35 h60
  text "X" at 13440,950 h60
  text "SILK" at 13576.46,950.35 h60
  text ".Layer_Name" at 577,-858.49 h60
M11 Gerber Information:
  lines w10: -292,-930.17 6308,-930.17 ; -292,-726.83 6310,-726.83 ; -292,-523.5 -292,-1133.5 3713,-1133.5 6310,-1133.5 6310,-523.5 -291.5,-523.5 -291.5,-1133.5 1284,-1133.5 ; 2173,-1133.5 2173,-523.5 ; 3440,-726.83 3440,-523.5 ; 4280,-726.83 4280,-523.5 ; 4902,-1140 4902,-937.17
  text "ALL ARTWORK VIEWED FROM TOP SIDE" at -228.5,-655.67 h60
  text "BOARD #:" at 2248,-655.67 h60
  text ".PRJ_Number" at 2793.5,-655.67 h60
  text "REV:" at 3638,-655.67 h60
  text ".PCB_Rev" at 3929.5,-655.67 h60
  text "SVN REV:" at 4476,-655.67 h60
  text ".VersionControl_RevNumber" at 4982,-655.67 h60
  text "LAYER NAME =" at -228.5,-858.49 h60
  text "PLOT NAME =" at -228.5,-1064.34 h60
  text ".plot_File_Name" at 577,-1064.34 h60
  text "GENERATED    :" at 2250,-1064.34 h60
  text ".Print_Date" at 3119.5,-1064.34 h60
  text ".Print_Time" at 3848.5,-1064.34 h60
  text "TEXAS INSTRUMENTS" at 5113,-1064.34 h60
M12 Stackup:
  lines w6: 11360,7460 13910,7460 ; 11360,7564.4 13910,7564.4 ; 11300,6975 ccw(c11334,6975) 11334,6941 13936,6941 ccw(c13936,6975) 13970,6975 13970,7681 ccw(c13936,7681) 13936,7715 11334,7715 ccw(c11334,7681) 11300,7681 11300,6975
  text "The Stackup Legend below this is static." at 11605.5,7874.5 h60
  text "If you change the stackup, update the Legend." at 11615.5,7784.5 h60
  text "Layer Stack Up Detail for: Ref_Design.PcbDoc" at 11360,7597.1 h57
  text "Layer" at 11360,7525.4 h24
  text "Gerber" at 12255.81,7525.4 h24
  text "Copper" at 12819.33,7525.4 h24
  text "Dielectric" at 13422.04,7525.4 h24
  text "Name" at 11360,7477.4 h24
  text "Document" at 12255.81,7477.4 h24
  text "Thickness" at 12819.33,7477.4 h24
  text "Material" at 13422.04,7477.4 h24
  text "Top Solder Mask" at 11360,7384.44 h34
  text "(.GTS)" at 12255.81,7384.44 h34
  text "Solder Resist" at 13422.04,7384.44 h34
  text "Top Layer" at 11360,7287.69 h34
  text "(.GTL)" at 12255.81,7287.69 h34
  text "1.4mil" at 12819.33,7287.69 h34
  text "FR-4" at 13422.04,7239.31 h34
  text "Bottom Layer" at 11360,7190.94 h34
  text "(.GBL)" at 12255.81,7190.94 h34
  text "1.4mil" at 12819.33,7190.94 h34
  text "Bottom Solder Mask" at 11360,7094.19 h34
  text "(.GBS)" at 12255.81,7094.19 h34
  text "Solder Resist" at 13422.04,7094.19 h34
  text ".Layer_Name" at 577,-858.49 h60
M13 Component Bodies Top:
  text ".Layer_Name" at 577,-858.49 h60
M14 Component Bodies Bottom:
  text ".Layer_Name" at 577,-858.49 h60
M15 Courtyards Top:
  text ".Layer_Name" at 577,-858.49 h60
M16 Courtyards Bottom:
  text ".Layer_Name" at 577,-858.49 h60
Drill Drawing:
  text ".legend" at 5122.5,725.5 h60
  text "Drill Table" at 5147.5,540.5 h60
  text ".Layer_Name" at 577,-858.49 h60

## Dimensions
0,0 to 3700,0 on M2 Board Dimensions
0,0 to 0,3100 on M2 Board Dimensions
